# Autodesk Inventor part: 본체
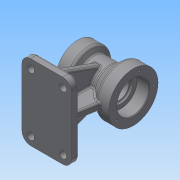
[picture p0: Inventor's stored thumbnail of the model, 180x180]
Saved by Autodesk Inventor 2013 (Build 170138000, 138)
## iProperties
Created: 2015-08
Part Number: 본체
Material: 일반
Document SubType Name: Modeling
Designer: Administrator
Density: 1 g/cm^3
Author: Administrator
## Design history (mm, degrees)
sketch "스케치1"
  geometry: L1 (0, 0)-(-40, 0); L2 (0, 0)-(50, 0); L3 (-40, 0)-(-40, 35); L4 (-40, 35)-(-20, 35); L5 (-20, 35)-(-14.804, 26); L6 (-14.804, 26)-(13.315, 26); L7 (13.315, 26)-(30, 40); L8 (30, 40)-(50, 40); L9 (50, 40)-(50, 0)
  constraints: 18 end point, 3 parallel, 2 perpendicular, 1 collinear, 1 horizontal
  dimensions: "d3" = 40 distance of L1.start L1.end; "d4" = 50 distance of L1.start L2.end; "d5" = 70 diameter of L4 L1; "d6" = 20 distance of L3.end L4.end; "d7" = 60 deg angle of L6 L5; "d8" = 52 diameter of L6 L1; "d9" = 80 diameter of L8 L2; "d10" = 20 distance of L7.end L8.end; "d11" = 40 deg angle of L6 L7
revolve "회전1" sketch "스케치1" stored, may be unused: angle "d12" = 90 deg
node "작업 평면1"
sketch "스케치2"
  geometry: L1 (40, 61)-(-40, 61); L2 (-40, 61)-(-40, -61); L3 (-40, -61)-(40, -61); L4 (40, -61)-(40, 61); L5 (40, 61)-(-40, -61); L6 (-40, 61)-(40, -61); 1 further point
  constraints: 12 end point, 2 midpoint, 2 parallel, 1 horizontal, 1 perpendicular
  dimensions: "d14" = 122 distance of L3.end L1.start; "d16" = 80 distance of L2.end L3.end
extrude "돌출1" join sketch "스케치2" distance "d17" = 12; taper "d18" = 0 deg
sketch "스케치3"
  geometry: L1 (-78, -61)-(-78, 61) reference; L2 (-90, -61)-(-78, -61) reference; L3 (-90, 85.4)-(-90, -85.4) reference; L4 (-6.815, -25.091)-(-78, -51); L5 (-78, 51)-(-6.815, 25.091); L6 (-90, 61)-(-78, 61) reference; C1 r 35 at (0, 0) reference; A1 r 26 centre (0, 0) between (-6.815, -25.091) and (-6.815, 25.091) reference; 1 further point
  constraints: 4 end point, 2 point on circle, 2 point on line
  dimensions: "d19" = 10 distance from line of L2 L4.end; "d20" = 70 deg angle of L1 L4; "d21" = 70 deg angle of L1 L5; "d22" = 10 distance from line of L6 L5.start
extrude "돌출2" join sketch "스케치3" stored distance "d23" = 12; taper "d24" = 0 deg
sketch "스케치4"
  geometry: L1 (-40, -35)-(-20, -35) reference; L2 (30, -40)-(50, -40) reference; L3 (13.315, -26)-(30, -40) reference; L4 (-14.804, -26)-(-14.804, 26) reference; L5 (-6, -6.815)-(-6, -6.815) reference; L6 (-6, -6.815)-(6, -6.815) reference; L7 (6, -6.815)-(6, -6.815) reference; L8 (6, -6.815)-(-6, -6.815) reference; L9 (13.315, -26)-(13.315, 26) reference; L10 (-14.804, -26)-(-14.804, 26) reference; L11 (-14.804, -26)-(-14.804, 26) reference; L12 (-20, -35)-(-20, 35) reference; L13 (40, -90)-(-40, -90) reference; L14 (-40, -90)-(-40, -78) reference; L15 (40, -78)-(-40, -78) reference; L16 (40, -90)-(40, -78) reference; L17 (-14.804, -26)-(13.315, -26) reference; L18 (-30, -78)-(-30, -35); L19 (30, -78)-(36.7, -40); 1 further point
  constraints: 4 end point, 3 point on line, 1 midpoint, 1 perpendicular
  dimensions: "d25" = 10 distance between parallel lines of L18 L14; "d26" = 80 deg angle of L15 L19; "d27" = 10 distance from line of L16 L19.start
  node "투영된 루프2"
  node "투영된 루프3"
  node "투영된 루프4"
feature "리브1" dims "d28" = 1, "d29" = 12, "d30" = 0, "d31" = 0, "d32" = 1, "d33" = 1
feature "리브2" dims "d34" = 1, "d35" = 12, "d36" = 0, "d37" = 0, "d38" = 1, "d39" = 1
sketch "스케치5"
  geometry: L1 (-6, -78)-(-6, -25.298) reference; L2 (-6, -78)-(-51, -78) reference; L3 (-6, -25.298)-(-6, -78) reference; L4 (-18, -54)-(-18, -60); L5 (-30, -54)-(-30, -60); A1 r 6 centre (-24, -54) between (-18, -54) and (-30, -54); A2 r 6 centre (-24, -60) between (-30, -60) and (-18, -60); A3 r 26 centre (0, 0) between (-25.091, -6.815) and (-6, -25.298) reference
  constraints: 4 end point, 4 point on circle, 2 centre point, 2 parallel, 2 tangent, 1 equal radius, 1 vertical alignment
  dimensions: "d40" = 12 diameter of A1; "d43" = 18 distance from line of L2 A2.centre; "d47" = 6 distance of A2.centre A1.centre; "d106" = 24 horizontal distance of A3.centre A2.centre
extrude "돌출3" cut sketch "스케치5" stored distance "d45" = 12; taper "d46" = 0 deg
sketch "스케치6"
  geometry: C1 r 40 at (0, 0) reference
hole "구멍1" sketch "스케치6" at (0, 0) diameter "d49" = 38; stored, may be unused: countersink angle "d53" = 90 deg, drill point angle "d55" = 0 deg; dims "d50" = 6, "d51" = 52, "d52" = 20, "d54" = 23
sketch "스케치7"
  geometry: C1 r 35 at (0, 0) reference
hole "구멍2" sketch "스케치7" at (0, 0) diameter "d56" = 32; stored, may be unused: countersink angle "d60" = 90 deg, drill point angle "d62" = 0 deg; dims "d57" = 6, "d58" = 40, "d59" = 17, "d61" = 23
sketch "스케치8"
  geometry: C1 r 26 at (0, 0) reference; 1 further point
  constraints: 1 vertical alignment
  dimensions: "d63" = 33 distance of C1.centre point (0, 33)
hole "구멍3" sketch "스케치8" at (0, 33) diameter "d64" = 3.242; stored, may be unused: countersink angle "d68" = 90 deg, drill point angle "d70" = 118 deg; dims "d65" = 10, "d66" = 40, "d67" = 17, "d69" = 13
sketch "스케치9"
  geometry: C1 r 20 at (0, 0) reference; 1 further point
  constraints: 1 vertical alignment
  dimensions: "d74" = 27 distance of C1.centre point (0, 27)
hole "구멍4" sketch "스케치9" at (0, 27) diameter "d75" = 3.242; stored, may be unused: countersink angle "d79" = 90 deg, drill point angle "d81" = 118 deg; dims "d76" = 10, "d77" = 40, "d78" = 17, "d80" = 13
chamfer "모따기1" distance "d85" = 1; stored, may be unused: second distance "d86" = 2, angle "d87" = 45 deg
fillet "모깎기1" dims "d88" = 0.3
fillet "모깎기2" dims "d89" = 3
fillet "모깎기3" dims "d90" = 0.3
fillet "모깎기4" dims "d91" = 5
fillet "모깎기5" dims "d92" = 14
sketch "스케치10"
  geometry: C1 r 6 at (26, 47); C2 r 6 at (26, -47); C3 r 6 at (-26, -47); C4 r 6 at (-26, 47); A1 r 14 centre (-26, -47) between (-40, -47) and (-26, -61) reference; A2 r 14 centre (26, -47) between (26, -61) and (40, -47) reference; A3 r 14 centre (26, 47) between (40, 47) and (26, 61) reference; A4 r 14 centre (-26, 47) between (-26, 61) and (-40, 47) reference; 1 further point
  constraints: 4 centre point, 4 coincident, 3 equal radius
  dimensions: "d93" = 12 diameter of C1
extrude "돌출4" cut sketch "스케치10" stored distance "d95" = 12; taper "d96" = 0 deg
fillet "모깎기6" dims "d97" = 3
fillet "모깎기7" dims "d98" = 3
fillet "모깎기8" dims "d99" = 3
fillet "모깎기9" dims "d100" = 3
fillet "모깎기10" dims "d101" = 3
sketch "스케치13"
  geometry: L1 (-3, 37.119)-(-3, 0) reference; L2 (-10, -3)-(1, -3) reference; 2 further points
  constraints: 1 other
  dimensions: "d102" = 16 distance from line of L1 point (13, 21); "d103" = 24 distance from line of point (13, 21) L2
feature "엠보싱1" sketch "스케치13" dims "d104" = 0.5, "d105" = 0
node "솔리드1"
mirror "대칭1"
pattern_circular "원형 패턴1" dims angle "d72" = 360 deg
pattern_circular "원형 패턴2" dims angle "d83" = 360 deg
node "투영된 루프1"
